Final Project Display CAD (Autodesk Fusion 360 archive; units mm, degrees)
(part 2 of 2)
sketch "Sketch40" plane through (0, 0, 0) normal (0, -1, 0) x axis (1, 0, 0)
  line L1 (-95.12, 65.595) -> (95.12, 65.595)
  line L2 (-95.12, -65.595) -> (-95.12, 65.595)
  line L3 (95.12, -65.595) -> (-95.12, -65.595)
  line L4 (95.12, 65.595) -> (95.12, -65.595)
  circle C1 centre (-90.12, 60.595) radius 2.25
extrude "Extrude52" cut sketch "Sketch40" profile of C1 against normal blind 10
component_from_bodies "Body->Comp4"
offset_faces "OffsetFaces1"
offset_faces "OffsetFaces1"
fillet "Fillet1" radius 0.5
fillet "Fillet1" radius 0.5 0.5
mirror "Mirror8" mirrorStitchTolerance 0.1
copy_paste "CutPaste1"
copy_paste "CutPaste2"
mirror_component "MirrorComponent2"
derived_instance "DerivedInstance3"
derived_instance "DerivedInstance1"
derived_instance "DerivedInstance2"
component_from_bodies "Body->Comp5"
split "Split9" bodies "Suction Cup", "Suction Cup (1)", "Suction Cup (2)", "Suction Cup (3)"
move "Move5"
extrude "Extrude53" cut of existing geometry blind -20
sketch "Sketch41" plane through (0, 6.35, 0) normal (0, 1, 0) x axis (-1, 0, 0)
  line L1 (147.12, -97.595) -> (-147.12, -97.595)
  line L2 (147.12, 137.595) -> (147.12, -97.595)
  line L3 (-147.12, 137.595) -> (147.12, 137.595)
  line L4 (-147.12, -97.595) -> (-147.12, 137.595)
  line L5 (107.12, 53.595) -> (107.12, 67.595)
  line L6 (97.12, 53.595) -> (107.12, 53.595)
  line L7 (97.12, -67.595) -> (97.12, 53.595)
  line L8 (-97.12, -67.595) -> (97.12, -67.595)
  line L9 (-97.12, 53.595) -> (-97.12, -67.595)
  line L10 (-107.12, 53.595) -> (-97.12, 53.595)
  line L11 (-107.12, 67.595) -> (-107.12, 53.595)
  line L12 (107.12, 67.595) -> (-107.12, 67.595)
  circle C1 centre (-135.5, 88.1) radius 2
  circle C2 centre (-126.5, 88.1) radius 2
  circle C3 centre (-135.5, 13.9214) radius 2
  circle C4 centre (-126.5, 13.9214) radius 2
  circle C5 centre (102.62, 71.595) radius 2
  circle C6 centre (-102.62, 71.595) radius 2
  circle C7 centre (-122.2834, -73.1497) radius 14.8661
  circle C8 centre (-122.2834, 113.1497) radius 14.8661
  circle C9 centre (122.2834, 113.1497) radius 14.8661
  circle C10 centre (122.2834, -73.1497) radius 14.8661
  circle C11 centre (-122.2834, 113.1497) radius 2
  circle C12 centre (-122.2834, -73.1497) radius 2
  circle C13 centre (122.2834, -73.1497) radius 2
  circle C14 centre (122.2834, 113.1497) radius 2
  concentric C8 C11
  concentric C7 C12
  concentric C10 C13
  concentric C9 C14
  dimension "d290" diameter C11 = 4
  dimension "d291" diameter C12 = 4
  dimension "d292" diameter C13 = 4
  dimension "d293" diameter C14 = 4
extrude "Extrude54" cut sketch "Sketch41" profile of C11 C12 C13 C14 to an object
component_from_bodies "Body->Comp6"
component_from_bodies "Body->Comp7"
sketch "Laser Cut Frame" plane through (0, 3.175, 0) normal (0, -1, 0) x axis (1, 0, 0)
  line L1 (107.12, 67.595) -> (-107.12, 67.595)
  line L2 (107.12, 53.595) -> (107.12, 67.595)
  line L3 (97.12, 53.595) -> (107.12, 53.595)
  line L4 (97.12, -67.595) -> (97.12, 53.595)
  line L5 (-97.12, -67.595) -> (97.12, -67.595)
  line L6 (-97.12, 53.595) -> (-97.12, -67.595)
  line L7 (-107.12, 53.595) -> (-97.12, 53.595)
  line L8 (-107.12, 67.595) -> (-107.12, 53.595)
  line L9 (147.12, -97.595) -> (-147.12, -97.595)
  line L10 (147.12, 137.595) -> (147.12, -97.595)
  line L11 (-147.12, 137.595) -> (147.12, 137.595)
  line L12 (-147.12, -97.595) -> (-147.12, 137.595)
  circle C1 centre (122.2834, -73.1497) radius 2
  circle C2 centre (-122.2834, -73.1497) radius 2
  circle C3 centre (122.2834, 113.1497) radius 2
  circle C4 centre (-122.2834, 113.1497) radius 2
  circle C5 centre (126.5, 13.9214) radius 2
  circle C6 centre (135.5, 13.9214) radius 2
  circle C7 centre (135.5, 88.1) radius 2
  circle C8 centre (126.5, 88.1) radius 2
  circle C9 centre (-102.62, 71.595) radius 2
  circle C10 centre (102.62, 71.595) radius 2
sketch "Sketch43" plane through (0, 3.175, 0) normal (0, -1, 0) x axis (1, 0, 0)
  line L1 (107.12, 67.595) -> (-107.12, 67.595)
  line L2 (107.12, 53.595) -> (107.12, 67.595)
  line L3 (97.12, 53.595) -> (107.12, 53.595)
  line L4 (97.12, -67.595) -> (97.12, 53.595)
  line L5 (-97.12, -67.595) -> (97.12, -67.595)
  line L6 (-97.12, 53.595) -> (-97.12, -67.595)
  line L7 (-107.12, 53.595) -> (-97.12, 53.595)
  line L8 (-107.12, 67.595) -> (-107.12, 53.595)
  line L9 (147.12, -97.595) -> (-147.12, -97.595)
  line L10 (147.12, 137.595) -> (147.12, -97.595)
  line L11 (-147.12, 137.595) -> (147.12, 137.595)
  line L12 (-147.12, -97.595) -> (-147.12, 137.595)
  line L13 (-75, 127.595) -> (75, 127.595)
  line L14 (-75, 87.595) -> (-75, 127.595)
  line L15 (75, 87.595) -> (-75, 87.595)
  line L16 (75, 127.595) -> (75, 87.595)
  line L17 (-75, 87.595) -> (75, 127.595)
  line L18 (75, 87.595) -> (-75, 127.595)
  line L19 (147.12, 137.595) -> (-147.12, 137.595)
  line L20 (0, 167.595) -> (0, 107.595)
  circle C1 centre (122.2834, -73.1497) radius 2
  circle C2 centre (-122.2834, -73.1497) radius 2
  circle C3 centre (122.2834, 113.1497) radius 2
  circle C4 centre (-122.2834, 113.1497) radius 2
  circle C5 centre (126.5, 13.9214) radius 2
  circle C6 centre (135.5, 13.9214) radius 2
  circle C7 centre (135.5, 88.1) radius 2
  circle C8 centre (126.5, 88.1) radius 2
  circle C9 centre (-102.62, 71.595) radius 2
  circle C10 centre (102.62, 71.595) radius 2
  point P28 (0, 107.595)
  point P31 (0, 107.595)
  point P26 (-75, 87.595)
  point P27 (75, 87.595)
  point P25 (-75, 127.595)
  horizontal L13
  perpendicular L13 L14
  parallel L13 L15
  parallel L14 L16
  coincident L17 P28
  coincident L18 P28
  coincident P28 P31
  perpendicular L19 L20
  midpoint L11 L20
  dimension "d296" distance P26 P27 = 150
  dimension "d297" distance P25 P26 = 40
  dimension "d309" distance L11 L13 = 10
extrude "Extrude1" add sketch "Sketch43" profile of L13 L14 L15 L16 along normal blind 60
split "Split1"
shell "Shell1" innerThickness 2
position "Position4"
sketch "Sketch44" plane through (0, 2.9298, 0) normal (0, -1, 0) x axis (1, 0, 0)
  line L1 (106.5117, 68.1997) -> (-107.7283, 68.1997)
  line L2 (106.5117, 54.1997) -> (106.5117, 68.1997)
  line L3 (96.5117, 54.1997) -> (106.5117, 54.1997)
  line L4 (96.5117, -66.9903) -> (96.5117, 54.1997)
  line L5 (-97.7283, -66.9903) -> (96.5117, -66.9903)
  line L6 (-97.7283, 54.1997) -> (-97.7283, -66.9903)
  line L7 (-107.7283, 54.1997) -> (-97.7283, 54.1997)
  line L8 (-107.7283, 68.1997) -> (-107.7283, 54.1997)
  line L9 (146.5117, -96.9903) -> (-147.7283, -96.9903)
  line L10 (146.5117, 138.1997) -> (146.5117, -96.9903)
  line L11 (-147.7283, 138.1997) -> (146.5117, 138.1997)
  line L12 (-147.7283, -96.9903) -> (-147.7283, 138.1997)
  line L13 (-0.6083, 70.1997) -> (-0.6083, 68.1997)
  line L14 (-3.8631, 70.1997) -> (-0.6083, 70.1997)
  line L15 (11.6417, 71.6997) -> (-12.8583, 71.6997)
  line L16 (-0.6083, 71.6997) -> (-0.6083, 70.1997)
  line L17 (-0.6083, 76.9497) -> (-0.6083, 71.6997)
  line L18 (7, 76.9497) -> (-0.6083, 76.9497)
  circle C1 centre (121.6751, -72.545) radius 2
  circle C2 centre (-122.8918, -72.545) radius 2
  circle C3 centre (121.6751, 113.7544) radius 2
  circle C4 centre (-122.8918, 113.7544) radius 2
  circle C5 centre (125.8917, 14.5261) radius 2
  circle C6 centre (134.8917, 14.5261) radius 2
  circle C7 centre (134.8917, 88.7047) radius 2
  circle C8 centre (125.8917, 88.7047) radius 2
  circle C9 centre (-103.2283, 72.1997) radius 2
  circle C10 centre (102.0117, 72.1997) radius 2
  circle C11 centre (-12.8583, 71.6997) radius 1.5
  circle C12 centre (11.6417, 71.6997) radius 1.5
  circle C13 centre (11.6417, 82.1997) radius 1.5
  circle C14 centre (-12.8583, 82.1997) radius 1.5
  point P24 (-0.6083, 68.1997)
  point P26 (-12.8583, 71.6997)
  point P29 (-12.8583, 71.6997)
  point P27 (11.6417, 71.6997)
  point P30 (11.6417, 71.6997)
  point P31 (-0.6083, 71.6997)
  point P28 (-3.8631, 70.1997)
  point P32 (-3.8631, 70.1997)
  point P33 (-0.6083, 71.6997)
  point P34 (-0.6083, 71.6997)
  point P25 (-0.6083, 70.1997)
  point P35 (-0.6083, 76.9497)
  midpoint L1 P24
  perpendicular L1 L13
  perpendicular L13 L14
  tangent C11 L14
  tangent C12 L14
  coincident P26 P29
  coincident P27 P30
  midpoint L15 P31
  coincident P28 P32
  coincident P31 P33
  vertical L16
  coincident P31 P34
  perpendicular L15 L17
  perpendicular L17 L18
  symmetric C11 L18 C14
  symmetric C12 L18 C13
  dimension "d301" distance P24 P25 = 2
  dimension "d304" distance C11 C12 = 21.5
  dimension "d306" diameter C12 = 3
  dimension "d307" diameter C11 = 3
  dimension "d308" distance P34 P35 = 5.25 (= "( 10.5 / 2 ) * 1 mm")
extrude "Extrude2" cut sketch "Sketch44" profile of C11 C12 C13 C14 against normal blind 10
sketch "Sketch45" plane through (0, 0, 88.1997) normal (0, 0, -1) x axis (1, 0, 0)
  line L1 (74.3917, -2.9298) -> (-75.6083, -2.9298)
  line L2 (74.3917, 57.0702) -> (74.3917, -2.9298)
  line L3 (-75.6083, 57.0702) -> (74.3917, 57.0702)
  line L4 (-75.6083, -2.9298) -> (-75.6083, 57.0702)
  line L5 (-9, 4.0702) -> (9, 4.0702)
  line L6 (-9, 1.0702) -> (-9, 4.0702)
  line L7 (9, 1.0702) -> (-9, 1.0702)
  line L8 (9, 4.0702) -> (9, 1.0702)
  line L9 (-9, 1.0702) -> (9, 4.0702)
  line L10 (9, 1.0702) -> (-9, 4.0702)
  point P10 (0, 2.5702)
  point P8 (-9, 1.0702)
  point P9 (9, 1.0702)
  point P7 (-9, 4.0702)
  horizontal L5
  perpendicular L5 L6
  parallel L5 L7
  parallel L6 L8
  coincident L9 P10
  coincident L10 P10
  dimension "d316" distance P8 P9 = 18
  dimension "d317" distance P7 P8 = 3
  dimension "d318" distance L1 L7 = 4
extrude "Extrude3" cut sketch "Sketch45" profile of L5 L6 L7 L8 to an object
sketch "Sketch46" plane through (0, 0.9298, 0) normal (0, -1, 0) x axis (1, 0, 0)
  line L1 (72.3917, 90.1997) -> (-73.6083, 90.1997)
  line L2 (72.3917, 126.1997) -> (72.3917, 90.1997)
  line L3 (-73.6083, 126.1997) -> (72.3917, 126.1997)
  line L4 (-73.6083, 90.1997) -> (-73.6083, 126.1997)
  line L5 (-68.6083, 126.1997) -> (-73.6083, 126.1997)
  line L6 (-68.6083, 121.1997) -> (-68.6083, 126.1997)
  line L7 (-73.6083, 121.1997) -> (-68.6083, 121.1997)
  line L8 (-73.6083, 126.1997) -> (-73.6083, 121.1997)
  circle C1 centre (-68.6083, 121.1997) radius 1.75
  point P5 (-73.6083, 126.1997)
  point P6 (-73.6083, 126.1997)
  point P8 (-68.6083, 121.1997)
  point P10 (-68.6083, 121.1997)
  point P7 (-68.6083, 126.1997)
  point P9 (-73.6083, 121.1997)
  horizontal L5
  vertical L6
  horizontal L7
  vertical L8
  coincident P5 P6
  coincident P8 P10
  dimension "d319" distance P6 P7 = 5
  dimension "d320" distance P6 P9 = 5
  dimension "d321" diameter C1 = 3.5
extrude "Extrude4" cut sketch "Sketch46" profile of L6 L7 C1 against normal blind 10
work_plane "WorkPlane6"
mirror "Mirror1" mirrorStitchTolerance 0.1
work_plane "WorkPlane7"
mirror "Mirror2" mirrorStitchTolerance 0.1
sketch "Sketch47" plane through (0, 0.9298, 0) normal (0, -1, 0) x axis (1, 0, 0)
  line L1 (72.3917, 90.1997) -> (-73.6083, 90.1997)
  line L2 (72.3917, 126.1997) -> (72.3917, 90.1997)
  line L3 (-73.6083, 126.1997) -> (72.3917, 126.1997)
  line L4 (-73.6083, 90.1997) -> (-73.6083, 126.1997)
  line L5 (-75.6083, 128.1997) -> (74.3917, 128.1997)
  line L6 (74.3917, 128.1997) -> (74.3917, 88.1997)
  line L7 (70.3917, 128.1997) -> (74.3917, 128.1997)
  line L8 (70.3917, 124.1997) -> (70.3917, 128.1997)
  line L9 (74.3917, 124.1997) -> (70.3917, 124.1997)
  line L10 (74.3917, 128.1997) -> (74.3917, 124.1997)
  circle C1 centre (67.3917, 95.1997) radius 1.75
  circle C2 centre (-68.6083, 95.1997) radius 1.75
  circle C3 centre (67.3917, 121.1997) radius 1.75
  circle C4 centre (-68.6083, 121.1997) radius 1.75
  circle C5 centre (72.3917, 126.1997) radius 1.5
  point P8 (72.3917, 126.1997)
  point P10 (72.3917, 126.1997)
  point P11 (74.3917, 128.1997)
  point P14 (74.3917, 128.1997)
  point P15 (70.3917, 128.1997)
  point P17 (74.3917, 124.1997)
  coincident P8 P10
  horizontal L7
  vertical L8
  horizontal L9
  vertical L10
  coincident P11 P14
  dimension "d328" diameter C5 = 3
  dimension "d329" distance P14 P15 = 4
  dimension "d330" distance P14 P17 = 4
extrude "Extrude5" add sketch "Sketch47" profile of L2 L3 L8 L9 along normal blind 58
sketch "Sketch48" plane through (0, -57.0702, 0) normal (0, -1, 0) x axis (1, 0, 0)
  line L1 (-73.6083, 90.1997) -> (72.3917, 90.1997)
  line L2 (-73.6083, 126.1997) -> (-73.6083, 90.1997)
  line L3 (70.3917, 126.1997) -> (-73.6083, 126.1997)
  line L4 (70.3917, 124.1997) -> (70.3917, 126.1997)
  line L5 (72.3917, 124.1997) -> (70.3917, 124.1997)
  line L6 (72.3917, 90.1997) -> (72.3917, 124.1997)
  line L7 (74.3917, 128.1997) -> (74.3917, 88.1997)
  line L8 (-75.6083, 128.1997) -> (74.3917, 128.1997)
  line L9 (-75.6083, 88.1997) -> (-75.6083, 128.1997)
  line L10 (74.3917, 88.1997) -> (-75.6083, 88.1997)
  line L11 (70.3917, 124.1997) -> (74.3917, 128.1997)
  circle C1 centre (72.3917, 126.1997) radius 1.5
  point P9 (74.3917, 128.1997)
  point P12 (74.3917, 128.1997)
  point P6 (70.3917, 124.1997)
  point P13 (70.3917, 124.1997)
  point P14 (72.3917, 126.1997)
  coincident P9 P12
  coincident P6 P13
  midpoint L11 P14
  dimension "d333" diameter C1 = 3
extrude "Extrude6" cut sketch "Sketch48" profile of C1 against normal blind 10
mirror "Mirror3" mirrorStitchTolerance 0.1
mirror "Mirror4" mirrorStitchTolerance 0.1
mirror "Mirror5" mirrorStitchTolerance 0.1
mirror "Mirror6" mirrorStitchTolerance 0.1
mirror "Mirror7" mirrorStitchTolerance 0.1
thread "Thread2"
thread "Thread3"
thread "Thread4"
thread "Thread5"
sketch "Sketch49" plane through (0, -57.0702, 0) normal (0, -1, 0) x axis (1, 0, 0)
  curve K1 (71.4335, 127.0249) -> (71.9931, 124.7091)
  curve K2 (72.7902, 124.7091) -> (73.3498, 127.0249)
  curve K3 (-72.6502, 89.3745) -> (-73.2098, 91.6904)
  curve K4 (-74.0069, 91.6904) -> (-74.5665, 89.3745)
  curve K5 (-72.6502, 125.3745) -> (-73.2098, 127.6904)
  curve K6 (-74.0069, 127.6904) -> (-74.5665, 125.3745)
  line L1 (-71.6083, 90.1997) -> (70.3917, 90.1997)
  line L2 (-71.6083, 92.1997) -> (-71.6083, 90.1997)
  line L3 (-73.6083, 92.1997) -> (-71.6083, 92.1997)
  line L4 (-73.6083, 124.1997) -> (-73.6083, 92.1997)
  line L5 (-71.6083, 124.1997) -> (-73.6083, 124.1997)
  line L6 (-71.6083, 126.1997) -> (-71.6083, 124.1997)
  line L7 (70.3917, 126.1997) -> (-71.6083, 126.1997)
  line L8 (70.3917, 124.1997) -> (70.3917, 126.1997)
  line L9 (72.3917, 124.1997) -> (70.3917, 124.1997)
  line L10 (72.3917, 92.1997) -> (72.3917, 124.1997)
  line L11 (70.3917, 92.1997) -> (72.3917, 92.1997)
  line L12 (70.3917, 90.1997) -> (70.3917, 92.1997)
  line L13 (74.3917, 128.1997) -> (74.3917, 88.1997)
  line L14 (-75.6083, 128.1997) -> (74.3917, 128.1997)
  line L15 (-75.6083, 88.1997) -> (-75.6083, 128.1997)
  line L16 (74.3917, 88.1997) -> (-75.6083, 88.1997)
  line L17 (74.3917, 128.1997) -> (-75.6083, 128.1997)
  line L18 (74.3917, 88.1997) -> (74.3917, 128.1997)
  line L19 (-75.6083, 88.1997) -> (74.3917, 88.1997)
  line L20 (-75.6083, 128.1997) -> (-75.6083, 88.1997)
  arc A1 centre (72.3917, 126.1997) radius 1.2645 clockwise from (71.4335, 127.0249) to (73.3498, 127.0249)
  arc A2 centre (72.3917, 126.1997) radius 1.543 clockwise from (72.7902, 124.7091) to (71.9931, 124.7091)
  arc A3 centre (-73.6083, 90.1997) radius 1.2645 clockwise from (-72.6502, 89.3745) to (-74.5665, 89.3745)
  arc A4 centre (-73.6083, 90.1997) radius 1.543 clockwise from (-74.0069, 91.6904) to (-73.2098, 91.6904)
  arc A5 centre (-73.6083, 126.1997) radius 1.2645 clockwise from (-72.6502, 125.3745) to (-74.5665, 125.3745)
  arc A6 centre (-73.6083, 126.1997) radius 1.543 clockwise from (-74.0069, 127.6904) to (-73.2098, 127.6904)
  circle C1 centre (72.3917, 90.1997) radius 1.2645
  point P30 (74.3917, 88.1997)
  point P36 (74.3917, 88.1997)
  point P32 (-75.6083, 128.1997)
  point P34 (-75.6083, 128.1997)
  horizontal L17
  vertical L18
  horizontal L19
  vertical L20
  coincident P30 P36
  coincident P32 P34
extrude "Extrude7" new body sketch "Sketch49" along normal blind 2 bodies "Lid"
component_from_bodies "Body->Comp1"
position "Position5"
copy_paste "CutPaste1"
copy_paste_bodies "CutPasteBodies"
sketch "Sketch50" plane through (74.3801, 0, 0) normal (1, 0, 0) x axis (0, 1, 0)
  line L1 (3.418, 128.0778) -> (3.418, 88.0778)
  line L2 (-56.582, 128.0778) -> (3.418, 128.0778)
  line L3 (-56.582, 88.0778) -> (-56.582, 128.0778)
  line L4 (3.418, 88.0778) -> (-56.582, 88.0778)
  circle C1 centre (-8, 100) radius 2
  dimension "d348" diameter C1 = 4
extrude "Extrude1" cut sketch "Sketch50" profile of C1 to an object
fillet "Fillet1" radius 10
fillet "Fillet3" radius 10
extrude "Extrude8" cut of existing geometry blind -2
extrude "Extrude1" cut of existing geometry blind -2
fillet "Fillet5" radius 1
fillet "Fillet6" radius 1
fillet "Fillet7" radius 2
sketch "Sketch52" plane through (0, 3.418, 0) normal (0, -1, 0) x axis (1, 0, 0)
  line L1 (96.5001, -67.1122) -> (96.5001, 44.0778)
  line L2 (-97.7399, -67.1122) -> (96.5001, -67.1122)
  line L3 (-97.7399, 44.0778) -> (-97.7399, -67.1122)
  line L4 (-109.7399, 67.0778) -> (-109.7399, 56.0778)
  line L5 (107.5001, 68.0778) -> (-108.7399, 68.0778)
  line L6 (108.5001, 56.0778) -> (108.5001, 67.0778)
  line L7 (146.5001, -97.1122) -> (-147.7399, -97.1122)
  line L8 (146.5001, 138.0778) -> (146.5001, -97.1122)
  line L9 (-147.7399, 138.0778) -> (146.5001, 138.0778)
  line L10 (-147.7399, -97.1122) -> (-147.7399, 138.0778)
  line L11 (98.12, 64.595) -> (86.12, 64.595)
  line L12 (98.12, 76) -> (98.12, 64.595)
  line L13 (100.0001, 72.0778) -> (98.12, 72.0778)
  line L14 (100.0001, 75.5871) -> (100.0001, 72.0778)
  line L15 (85.1799, 77.595) -> (99.0601, 77.595)
  line L16 (85.1799, 77.7532) -> (85.1799, 77.595)
  line L17 (99.0601, 64.595) -> (99.0601, 77.595)
  line L18 (99.0601, 72.0778) -> (99.0601, 68.0778)
  line L19 (85.1799, 68.0778) -> (85.1799, 77.7532)
  line L20 (99.0601, 77.595) -> (99.0601, 72.0778)
  arc A1 centre (106.5001, 44.0778) radius 10 clockwise from (96.5001, 44.0778) to (106.5001, 54.0778)
  arc A2 centre (-107.7399, 44.0778) radius 10 clockwise from (-107.7399, 54.0778) to (-97.7399, 44.0778)
  arc A3 centre (-107.7399, 56.0778) radius 2 clockwise from (-107.7399, 54.0778) to (-109.7399, 56.0778)
  arc A4 centre (-108.7399, 67.0778) radius 1 clockwise from (-109.7399, 67.0778) to (-108.7399, 68.0778)
  arc A5 centre (107.5001, 67.0778) radius 1 clockwise from (107.5001, 68.0778) to (108.5001, 67.0778)
  arc A6 centre (106.5001, 56.0778) radius 2 clockwise from (108.5001, 56.0778) to (106.5001, 54.0778)
  circle C1 centre (67.3801, 95.0778) radius 1.75
  circle C2 centre (-68.6199, 95.0778) radius 1.75
  circle C3 centre (67.3801, 121.0778) radius 1.75
  circle C4 centre (-68.6199, 121.0778) radius 1.75
  circle C5 centre (-12.8699, 82.0778) radius 1.5
  circle C6 centre (-12.8699, 71.5778) radius 1.5
  circle C7 centre (11.6301, 82.0778) radius 1.5
  circle C8 centre (11.6301, 71.5778) radius 1.5
  circle C9 centre (121.6636, -72.667) radius 2
  circle C10 centre (-122.9033, -72.667) radius 2
  circle C11 centre (121.6636, 113.6325) radius 2
  circle C12 centre (-122.9033, 113.6325) radius 2
  circle C13 centre (125.8802, 14.4042) radius 2
  circle C14 centre (134.8802, 14.4042) radius 2
  circle C15 centre (134.8802, 88.5828) radius 2
  circle C16 centre (125.8802, 88.5828) radius 2
  circle C17 centre (-103.2399, 72.0778) radius 2
  circle C18 centre (102.0001, 72.0778) radius 2
  point P43 (98.12, 64.595)
  point P44 (98.12, 64.595)
  point P46 (98.12, 72.0778)
  point P47 (100.0001, 72.0778)
  point P52 (99.0601, 64.595)
  point P53 (99.0601, 68.0778)
  point P54 (99.0601, 72.0778)
  point P55 (85.1799, 68.0778)
  point P49 (99.0601, 77.595)
  point P42 (86.12, 64.595)
  point P51 (85.1799, 77.7532)
  coincident P43 P44
  perpendicular L11 L12
  coincident L12 P46
  coincident C18 P47
  perpendicular L12 L13
  tangent C18 L14
  vertical L14
  perpendicular L15 L16
  perpendicular L15 L17
  coincident L11 P52
  vertical L17
  coincident L17 P53
  coincident L5 P53
  midpoint L13 P54
  coincident L5 P55
  perpendicular L5 L19
  dimension "d371" distance P49 P52 = 13
  dimension "d372" distance P46 P47 = 1.8801
  dimension "d373" distance L12 L17 = 0.9401 (= "d372 / 2")
  dimension "d374" distance P42 P51 = 0.9401 (= "d373")
extrude "Extrude10" cut sketch "Sketch52" profile of L5 L15 L18 L19 L20 against normal blind 10
fillet "Fillet8" radius 20
fillet "Fillet9" radius 2
fillet "Fillet10" radius 2
mirror "Mirror8" mirrorStitchTolerance 0.1
fillet "Fillet11" radius 2 2
sketch "frame-laser" plane through (0, 3.418, 0) normal (0, -1, 0) x axis (1, 0, 0)
  line L1 (-145.7399, 138.0778) -> (144.5001, 138.0778)
  line L2 (-147.7399, -95.1122) -> (-147.7399, 136.0778)
  line L3 (144.5001, -97.1122) -> (-145.7399, -97.1122)
  line L4 (146.5001, 136.0778) -> (146.5001, -95.1122)
  line L5 (-100.2768, 75.595) -> (-100.2768, 70.0778)
  line L6 (-87.4797, 77.595) -> (-98.2768, 77.595)
  line L7 (68.1473, 68.0778) -> (-69.3639, 68.0778)
  line L8 (97.0601, 77.595) -> (86.263, 77.595)
  line L9 (99.0601, 70.0778) -> (99.0601, 75.595)
  line L10 (107.5001, 68.0778) -> (101.0601, 68.0778)
  line L11 (108.5001, 56.0778) -> (108.5001, 67.0778)
  line L12 (96.5001, -67.1122) -> (96.5001, 44.0778)
  line L13 (-97.7399, -67.1122) -> (96.5001, -67.1122)
  line L14 (-97.7399, 44.0778) -> (-97.7399, -67.1122)
  line L15 (-109.7399, 67.0778) -> (-109.7399, 56.0778)
  line L16 (-102.2768, 68.0778) -> (-108.7399, 68.0778)
  arc A1 centre (144.5001, 136.0778) radius 2 clockwise from (144.5001, 138.0778) to (146.5001, 136.0778)
  arc A2 centre (-145.7399, 136.0778) radius 2 clockwise from (-147.7399, 136.0778) to (-145.7399, 138.0778)
  arc A3 centre (-145.7399, -95.1122) radius 2 clockwise from (-145.7399, -97.1122) to (-147.7399, -95.1122)
  arc A4 centre (144.5001, -95.1122) radius 2 clockwise from (146.5001, -95.1122) to (144.5001, -97.1122)
  arc A5 centre (-102.2768, 70.0778) radius 2 clockwise from (-100.2768, 70.0778) to (-102.2768, 68.0778)
  arc A6 centre (-98.2768, 75.595) radius 2 clockwise from (-100.2768, 75.595) to (-98.2768, 77.595)
  arc A7 centre (-87.4797, 75.595) radius 2 clockwise from (-87.4797, 77.595) to (-85.8328, 76.7298)
  arc A8 centre (-69.3639, 88.0778) radius 20 clockwise from (-69.3639, 68.0778) to (-85.8328, 76.7298)
  arc A9 centre (68.1473, 88.0778) radius 20 clockwise from (84.6161, 76.7298) to (68.1473, 68.0778)
  arc A10 centre (86.263, 75.595) radius 2 clockwise from (84.6161, 76.7298) to (86.263, 77.595)
  arc A11 centre (97.0601, 75.595) radius 2 clockwise from (97.0601, 77.595) to (99.0601, 75.595)
  arc A12 centre (101.0601, 70.0778) radius 2 clockwise from (101.0601, 68.0778) to (99.0601, 70.0778)
  arc A13 centre (107.5001, 67.0778) radius 1 clockwise from (107.5001, 68.0778) to (108.5001, 67.0778)
  arc A14 centre (106.5001, 56.0778) radius 2 clockwise from (108.5001, 56.0778) to (106.5001, 54.0778)
  arc A15 centre (106.5001, 44.0778) radius 10 clockwise from (96.5001, 44.0778) to (106.5001, 54.0778)
  arc A16 centre (-107.7399, 44.0778) radius 10 clockwise from (-107.7399, 54.0778) to (-97.7399, 44.0778)
  arc A17 centre (-107.7399, 56.0778) radius 2 clockwise from (-107.7399, 54.0778) to (-109.7399, 56.0778)
  arc A18 centre (-108.7399, 67.0778) radius 1 clockwise from (-109.7399, 67.0778) to (-108.7399, 68.0778)
  circle C1 centre (102.0001, 72.0778) radius 2
  circle C2 centre (-103.2399, 72.0778) radius 2
  circle C3 centre (125.8802, 88.5828) radius 2
  circle C4 centre (134.8802, 88.5828) radius 2
  circle C5 centre (134.8802, 14.4042) radius 2
  circle C6 centre (125.8802, 14.4042) radius 2
  circle C7 centre (-122.9033, 113.6325) radius 2
  circle C8 centre (121.6636, 113.6325) radius 2
  circle C9 centre (-122.9033, -72.667) radius 2
  circle C10 centre (121.6636, -72.667) radius 2
  circle C11 centre (11.6301, 71.5778) radius 1.5
  circle C12 centre (11.6301, 82.0778) radius 1.5
  circle C13 centre (-12.8699, 71.5778) radius 1.5
  circle C14 centre (-12.8699, 82.0778) radius 1.5
  circle C15 centre (-68.6199, 121.0778) radius 1.75
  circle C16 centre (67.3801, 121.0778) radius 1.75
  circle C17 centre (-68.6199, 95.0778) radius 1.75
  circle C18 centre (67.3801, 95.0778) radius 1.75
sketch "Sketch55" plane through (0, -58.582, 0) normal (0, -1, 0) x axis (1, 0, 0)
  curve K1 (-74.0184, 127.5684) -> (-74.578, 125.2525)
  curve K2 (-72.6617, 125.2525) -> (-73.2213, 127.5684)
  curve K3 (-74.0184, 91.5684) -> (-74.578, 89.2525)
  curve K4 (-72.6617, 89.2525) -> (-73.2213, 91.5684)
  curve K5 (72.7787, 124.5871) -> (73.3383, 126.903)
  curve K6 (71.422, 126.903) -> (71.9816, 124.5871)
  line L1 (74.3801, 88.0778) -> (-75.6199, 88.0778)
  line L2 (74.3801, 128.0778) -> (74.3801, 88.0778)
  line L3 (-75.6199, 128.0778) -> (74.3801, 128.0778)
  line L4 (-75.6199, 88.0778) -> (-75.6199, 128.0778)
  line L5 (-75.6199, 90.0778) -> (-73.6199, 90.0778)
  line L6 (-73.6199, 88.0778) -> (-73.6199, 90.0778)
  line L7 (-75.6199, 126.0778) -> (-73.6199, 126.0778)
  line L8 (-73.6199, 128.0778) -> (-73.6199, 126.0778)
  line L9 (74.3801, 126.0778) -> (72.3801, 126.0778)
  line L10 (72.3801, 128.0778) -> (72.3801, 126.0778)
  line L11 (74.3801, 90.0778) -> (72.3801, 90.0778)
  line L12 (72.3801, 88.0778) -> (72.3801, 90.0778)
  arc A1 centre (-73.6199, 126.0778) radius 1.2645 clockwise from (-72.6617, 125.2525) to (-74.578, 125.2525)
  arc A2 centre (-73.6199, 126.0778) radius 1.543 clockwise from (-74.0184, 127.5684) to (-73.2213, 127.5684)
  arc A3 centre (-73.6199, 90.0778) radius 1.2645 clockwise from (-72.6617, 89.2525) to (-74.578, 89.2525)
  arc A4 centre (-73.6199, 90.0778) radius 1.543 clockwise from (-74.0184, 91.5684) to (-73.2213, 91.5684)
  arc A5 centre (72.3801, 126.0778) radius 1.2645 clockwise from (71.422, 126.903) to (73.3383, 126.903)
  arc A6 centre (72.3801, 126.0778) radius 1.543 clockwise from (72.7787, 124.5871) to (71.9816, 124.5871)
  circle C1 centre (72.3801, 90.0778) radius 1.2645
  circle C2 centre (-73.6199, 90.0778) radius 1.75
  circle C3 centre (-73.6199, 126.0778) radius 1.75
  circle C4 centre (72.3801, 126.0778) radius 1.75
  circle C5 centre (72.3801, 90.0778) radius 1.75
  point P9 (-73.6199, 90.0778)
  point P22 (-73.6199, 90.0778)
  point P23 (-75.6199, 90.0778)
  point P24 (-73.6199, 88.0778)
  point P25 (-73.6199, 90.0778)
  point P4 (-73.6199, 126.0778)
  point P26 (-73.6199, 126.0778)
  point P27 (-75.6199, 126.0778)
  point P28 (-73.6199, 128.0778)
  point P29 (-73.6199, 126.0778)
  point P14 (72.3801, 126.0778)
  point P30 (72.3801, 126.0778)
  point P31 (74.3801, 126.0778)
  point P32 (72.3801, 128.0778)
  point P33 (72.3801, 126.0778)
  point P17 (72.3801, 90.0778)
  point P34 (72.3801, 90.0778)
  point P35 (74.3801, 90.0778)
  point P36 (72.3801, 88.0778)
  point P37 (72.3801, 90.0778)
  coincident P9 P22
  coincident L4 P23
  perpendicular L4 L5
  coincident L1 P24
  perpendicular L1 L6
  coincident P22 P25
  coincident P4 P26
  coincident L4 P27
  perpendicular L4 L7
  coincident L3 P28
  perpendicular L3 L8
  coincident P26 P29
  coincident P14 P30
  coincident L2 P31
  perpendicular L2 L9
  coincident L3 P32
  perpendicular L3 L10
  coincident P30 P33
  coincident P17 P34
  coincident L2 P35
  perpendicular L2 L11
  coincident L1 P36
  perpendicular L1 L12
  coincident P34 P37
  dimension "d391" diameter C2 = 3.5
  dimension "d392" diameter C3 = 3.5
  dimension "d393" diameter C4 = 3.5
  dimension "d394" diameter C5 = 3.5
extrude "Extrude2" cut sketch "Sketch55" profile of A1 K1 A2 K2 A3 K3 A4 K4 A5 K5 A6 K6 C1 C2 C3 C4 C5 against normal blind 10
sketch "Sketch56" plane through (0, -58.582, 0) normal (0, -1, 0) x axis (1, 0, 0)
  line L1 (74.3801, 88.0778) -> (-75.6199, 88.0778)
  line L2 (74.3801, 128.0778) -> (74.3801, 88.0778)
  line L3 (-75.6199, 128.0778) -> (74.3801, 128.0778)
  line L4 (-75.6199, 88.0778) -> (-75.6199, 128.0778)
  line L5 (77.3801, 85.0778) -> (-78.6199, 85.0778)
  line L6 (77.3801, 131.0778) -> (77.3801, 85.0778)
  line L7 (-78.6199, 131.0778) -> (77.3801, 131.0778)
  line L8 (-78.6199, 85.0778) -> (-78.6199, 131.0778)
  circle C1 centre (72.3801, 126.0778) radius 1.75
  circle C2 centre (-73.6199, 126.0778) radius 1.75
  circle C3 centre (72.3801, 90.0778) radius 1.75
  circle C4 centre (-73.6199, 90.0778) radius 1.75
  dimension "d397" = 3
extrude "Extrude3" add sketch "Sketch56" profile of L1 L2 L3 L4 L5 L8 L6 L7 to an object
fillet "Fillet1" radius 2
sketch "Sketch57" plane through (0, -58.582, 0) normal (0, -1, 0) x axis (1, 0, 0)
  line L1 (75.3801, 85.0778) -> (-76.6199, 85.0778)
  line L2 (77.3801, 129.0778) -> (77.3801, 87.0778)
  line L3 (-76.6199, 131.0778) -> (75.3801, 131.0778)
  line L4 (-78.6199, 87.0778) -> (-78.6199, 129.0778)
  line L5 (76.7944, 85.6635) -> (-78.0341, 130.492)
  arc A1 centre (-76.6199, 87.0778) radius 2 clockwise from (-76.6199, 85.0778) to (-78.6199, 87.0778)
  arc A2 centre (75.3801, 87.0778) radius 2 clockwise from (77.3801, 87.0778) to (75.3801, 85.0778)
  arc A3 centre (75.3801, 129.0778) radius 2 clockwise from (75.3801, 131.0778) to (77.3801, 129.0778)
  arc A4 centre (-76.6199, 129.0778) radius 2 clockwise from (-78.6199, 129.0778) to (-76.6199, 131.0778)
  circle C1 centre (72.3801, 126.0778) radius 1.75
  circle C2 centre (-73.6199, 126.0778) radius 1.75
  circle C3 centre (72.3801, 90.0778) radius 1.75
  circle C4 centre (-73.6199, 90.0778) radius 1.75
  circle C5 centre (-0.6199, 108.0778) radius 3
  point P18 (-78.0341, 130.492)
  point P19 (76.7944, 85.6635)
  point P20 (-0.6199, 108.0778)
  midpoint A4 P18
  midpoint A2 P19
  midpoint L5 P20
  dimension "d402" diameter C5 = 6
extrude "Extrude4" cut sketch "Sketch57" profile of C5 against normal blind 10
sketch "Sketch59" plane through (-73.6199, 0, 0) normal (1, 0, 0) x axis (0, 1, 0)
  line L1 (-56.582, 124.0778) -> (1.418, 124.0778)
  line L2 (-56.582, 92.0778) -> (-56.582, 124.0778)
  line L3 (1.418, 92.0778) -> (-56.582, 92.0778)
  line L4 (1.418, 124.0778) -> (1.418, 92.0778)
  line L5 (-55.582, 108.0778) -> (-56.582, 108.0778)
  line L6 (-55.582, 101.0778) -> (-55.582, 108.0778)
  line L7 (-55.582, 115.0778) -> (-55.582, 108.0778)
  line L8 (-54.582, 101.0778) -> (-55.582, 101.0778)
  circle C1 centre (-54.582, 101.0778) radius 1
  circle C2 centre (-54.582, 115.0778) radius 1
  circle C3 centre (-54.582, 101.0778) radius 1.25
  circle C4 centre (-54.582, 115.0778) radius 1.25
  point P6 (-56.582, 108.0778)
  point P10 (-54.582, 101.0778)
  point P11 (-54.582, 101.0778)
  point P7 (-55.582, 108.0778)
  point P8 (-55.582, 101.0778)
  point P9 (-55.582, 115.0778)
  midpoint L2 P6
  perpendicular L2 L5
  perpendicular L5 L6
  perpendicular L5 L7
  tangent L6 C1
  coincident P10 P11
  horizontal L8
  symmetric L5 C1 C2
  concentric C1 C3
  concentric C2 C4
  dimension "d405" distance P6 P7 = 1
  dimension "d406" distance P7 P8 = 7
  dimension "d407" distance P7 P9 = 7
  dimension "d408" diameter C1 = 2
  dimension "d409" diameter C3 = 2.5
  dimension "d410" diameter C4 = 2.5
extrude "Extrude5" cut sketch "Sketch59" profile of C3 C4 against normal blind 10
sketch "Sketch60" plane through (0, -58.582, 0) normal (0, -1, 0) x axis (1, 0, 0)
  line L1 (75.3801, 85.0778) -> (-76.6199, 85.0778)
  line L2 (77.3801, 129.0778) -> (77.3801, 87.0778)
  line L3 (-76.6199, 131.0778) -> (75.3801, 131.0778)
  line L4 (-78.6199, 87.0778) -> (-78.6199, 129.0778)
  line L5 (-73.6199, 124.0778) -> (-73.6199, 92.0778)
  line L6 (-72.6199, 108.0778) -> (-73.6199, 108.0778)
  line L7 (-72.6199, 103.5778) -> (-72.6199, 108.0778)
  line L8 (-69.1199, 103.5778) -> (-72.6199, 103.5778)
  line L9 (-69.1199, 103.5778) -> (-72.6199, 103.5778)
  line L10 (-69.1199, 112.5778) -> (-69.1199, 103.5778)
  line L11 (-72.6199, 112.5778) -> (-69.1199, 112.5778)
  line L12 (-72.6199, 103.5778) -> (-72.6199, 112.5778)
  circle C1 centre (-0.6199, 108.0778) radius 3
  arc A1 centre (-76.6199, 87.0778) radius 2 clockwise from (-76.6199, 85.0778) to (-78.6199, 87.0778)
  arc A2 centre (75.3801, 87.0778) radius 2 clockwise from (77.3801, 87.0778) to (75.3801, 85.0778)
  arc A3 centre (75.3801, 129.0778) radius 2 clockwise from (75.3801, 131.0778) to (77.3801, 129.0778)
  arc A4 centre (-76.6199, 129.0778) radius 2 clockwise from (-78.6199, 129.0778) to (-76.6199, 131.0778)
  circle C2 centre (72.3801, 126.0778) radius 1.75
  circle C3 centre (-73.6199, 126.0778) radius 1.75
  circle C4 centre (72.3801, 90.0778) radius 1.75
  circle C5 centre (-73.6199, 90.0778) radius 1.75
  point P21 (-73.6199, 108.0778)
  point P22 (-72.6199, 108.0778)
  point P23 (-72.6199, 103.5778)
  point P24 (-69.1199, 103.5778)
  point P25 (-69.1199, 103.5778)
  point P27 (-72.6199, 112.5778)
  midpoint L5 P21
  perpendicular L5 L6
  perpendicular L6 L7
  perpendicular L7 L8
  horizontal L9
  vertical L10
  horizontal L11
  vertical L12
  dimension "d413" distance P21 P22 = 1
  dimension "d414" distance P22 P23 = 4.5
  dimension "d415" distance P23 P24 = 3.5
  dimension "d416" distance P23 P25 = 3.5
  dimension "d417" distance P23 P27 = 9
extrude "Extrude6" cut sketch "Sketch60" profile of L7 L8 L9 L10 L11 L12 against normal blind 10
fillet "Fillet2" radius 1
position "Position6"
sketch "Sketch61" plane through (0, -56.54, 0) normal (0, -1, 0) x axis (1, 0, 0)
  curve K1 (71.4082, 126.7865) -> (71.9678, 124.4707)
  curve K2 (72.7649, 124.4707) -> (73.3245, 126.7865)
  curve K3 (-72.6755, 89.1361) -> (-73.2351, 91.452)
  curve K4 (-74.0322, 91.452) -> (-74.5918, 89.1361)
  curve K5 (-72.6755, 125.1361) -> (-73.2351, 127.452)
  curve K6 (-74.0322, 127.452) -> (-74.5918, 125.1361)
  line L1 (-71.6336, 89.9613) -> (70.3664, 89.9613)
  line L2 (-71.6336, 91.9613) -> (-71.6336, 89.9613)
  line L3 (-73.6336, 91.9613) -> (-71.6336, 91.9613)
  line L4 (-73.6336, 123.9613) -> (-73.6336, 91.9613)
  line L5 (-71.6336, 123.9613) -> (-73.6336, 123.9613)
  line L6 (-71.6336, 125.9613) -> (-71.6336, 123.9613)
  line L7 (70.3664, 125.9613) -> (-71.6336, 125.9613)
  line L8 (70.3664, 123.9613) -> (70.3664, 125.9613)
  line L9 (72.3664, 123.9613) -> (70.3664, 123.9613)
  line L10 (72.3664, 91.9613) -> (72.3664, 123.9613)
  line L11 (70.3664, 91.9613) -> (72.3664, 91.9613)
  line L12 (70.3664, 89.9613) -> (70.3664, 91.9613)
  line L13 (74.3664, 127.9613) -> (74.3664, 87.9613)
  line L14 (-75.6336, 127.9613) -> (74.3664, 127.9613)
  line L15 (-75.6336, 87.9613) -> (-75.6336, 127.9613)
  line L16 (74.3664, 87.9613) -> (-75.6336, 87.9613)
  line L17 (77.3664, 84.9613) -> (-78.6336, 84.9613)
  line L18 (77.3664, 130.9613) -> (77.3664, 84.9613)
  line L19 (-80, 130.9613) -> (77.3664, 130.9613)
  line L20 (-78.6336, 84.9613) -> (-78.6336, 133)
  line L21 (-70.6336, 122.9613) -> (-73.6336, 122.9613)
  line L22 (-70.6336, 125.9613) -> (-70.6336, 122.9613)
  line L23 (-70.6336, 92.9613) -> (-70.6336, 89.9613)
  line L24 (-73.6336, 92.9613) -> (-70.6336, 92.9613)
  line L25 (69.3664, 92.9613) -> (72.3664, 92.9613)
  line L26 (69.3664, 89.9613) -> (69.3664, 92.9613)
  line L27 (69.3664, 122.9613) -> (69.3664, 125.9613)
  line L28 (72.3664, 122.9613) -> (69.3664, 122.9613)
  arc A1 centre (72.3664, 125.9613) radius 1.2645 clockwise from (71.4082, 126.7865) to (73.3245, 126.7865)
  arc A2 centre (72.3664, 125.9613) radius 1.543 clockwise from (72.7649, 124.4707) to (71.9678, 124.4707)
  arc A3 centre (-73.6336, 89.9613) radius 1.2645 clockwise from (-72.6755, 89.1361) to (-74.5918, 89.1361)
  arc A4 centre (-73.6336, 89.9613) radius 1.543 clockwise from (-74.0322, 91.452) to (-73.2351, 91.452)
  arc A5 centre (-73.6336, 125.9613) radius 1.2645 clockwise from (-72.6755, 125.1361) to (-74.5918, 125.1361)
  arc A6 centre (-73.6336, 125.9613) radius 1.543 clockwise from (-74.0322, 127.452) to (-73.2351, 127.452)
  circle C1 centre (72.3664, 89.9613) radius 1.2645
  dimension "d424" = 1
  dimension "d425" = 1
  dimension "d426" = 1
  dimension "d427" = 1
extrude "Extrude7" add sketch "Sketch61" profile of L1 L2 L3 L4 L5 L6 L7 L8 L9 L10 L11 L12 L13 L14 L15 L16 L19 L17 L20 L18 L21 L22 L23 L24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 to an object
fillet "Fillet3" radius 1 1
fillet "Fillet4" radius 2
extrude "Extrude8" cut of existing geometry blind -10
sketch "laser-lid" plane through (0, -58.54, 0) normal (0, -1, 0) x axis (1, 0, 0)
  line L1 (-71.6336, 103.4613) -> (-70.1336, 103.4613)
  line L2 (-72.6336, 111.4613) -> (-72.6336, 104.4613)
  line L3 (-70.1336, 112.4613) -> (-71.6336, 112.4613)
  line L4 (-69.1336, 104.4613) -> (-69.1336, 111.4613)
  line L5 (75.3664, 84.9613) -> (-76.6336, 84.9613)
  line L6 (77.3664, 128.9613) -> (77.3664, 86.9613)
  line L7 (-76.6336, 130.9613) -> (75.3664, 130.9613)
  line L8 (-78.6336, 86.9613) -> (-78.6336, 128.9613)
  arc A1 centre (-71.6336, 104.4613) radius 1 clockwise from (-71.6336, 103.4613) to (-72.6336, 104.4613)
  arc A2 centre (-71.6336, 111.4613) radius 1 clockwise from (-72.6336, 111.4613) to (-71.6336, 112.4613)
  arc A3 centre (-70.1336, 111.4613) radius 1 clockwise from (-70.1336, 112.4613) to (-69.1336, 111.4613)
  arc A4 centre (-70.1336, 104.4613) radius 1 clockwise from (-69.1336, 104.4613) to (-70.1336, 103.4613)
  circle C1 centre (-0.6336, 107.9613) radius 3
  arc A5 centre (-76.6336, 86.9613) radius 2 clockwise from (-76.6336, 84.9613) to (-78.6336, 86.9613)
  arc A6 centre (75.3664, 86.9613) radius 2 clockwise from (77.3664, 86.9613) to (75.3664, 84.9613)
  arc A7 centre (75.3664, 128.9613) radius 2 clockwise from (75.3664, 130.9613) to (77.3664, 128.9613)
  arc A8 centre (-76.6336, 128.9613) radius 2 clockwise from (-78.6336, 128.9613) to (-76.6336, 130.9613)
  circle C2 centre (72.3664, 125.9613) radius 1.75
  circle C3 centre (-73.6336, 125.9613) radius 1.75
  circle C4 centre (72.3664, 89.9613) radius 1.75
  circle C5 centre (-73.6336, 89.9613) radius 1.75
extrude "Extrude9" cut of existing geometry blind -10
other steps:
derived_base_feature "Derived Base Feature1"
derived_base_feature "Derived Base Feature1" bodies "CaseHinge1"
derived_base_feature "Derived Base Feature1" bodies "FrameHinge1"
base_feature "Base Feature1" bodies "Servo Mount"
base_feature "Base Feature1" bodies "Frame"
base_feature "Base Feature1" bodies "Case"
base_feature "Base Feature1" bodies "FrameHinge1"
base_feature "Base Feature1" bodies "CaseHinge1"
base_feature "Base Feature1" bodies "Frame (1)", "Case"
base_feature "Base Feature2" bodies "Lid"
base_feature "Base Feature1" bodies "Servo Arm Attachment"
base_feature "Base Feature1" bodies "Case Attachment"
extrude "Extrude9" cut of existing geometry blind -2
create_component "CreateComponent1"
remove_body "RemoveBody2"
create_component "CreateComponent2"
remove_body "RemoveBody3"
create_component "CreateComponent3"
remove_body "RemoveBody5"
create_component "CreateComponent4"
remove_body "RemoveBody6"
create_component "CreateComponent8"
remove_instance "RemoveInstance1"
remove_instance "RemoveInstance2"
create_component "CreateComponent9"
create_component "CreateComponent10"
create_component "CreateComponent11"
create_component "CreateComponent12"
remove_body "RemoveBody7"
create_component "CreateComponent13"
remove_body "RemoveBody8"
create_component "CreateComponent14"
remove_body "RemoveBody9"
create_component "CreateComponent1"
remove_body "RemoveBody1"
remove_instance "RemoveInstance1"
remove_body "RemoveBody2"
named bodies: "Case", "Frame", "Servo", "Servo Arm Attachment", "Case Attachment", "Case (2)", "Case (3)", "Case (2) (1)", "Case Attachment (1)", "Frame (1)", "FrameHinge1", "Frame (3)", "Frame (4)", "Servo Mount", "Servo Arm Attachment (1)", "Servo Arm Attachment (2)", "Servo Arm Attachment (3)", "Servo Arm Attachment (4)", "Servo Arm Attachment (5)", "Servo Arm Attachment (6)", "Servo Arm Attachment (7)", "Servo Arm Attachment (8)", "Servo Arm Attachment (9)", "Servo Arm Attachment (10)", "Servo Arm Attachment (11)", "Servo Arm Attachment (12)", "Servo Arm Attachment (13)", "Servo Arm Attachment (14)", "Servo Arm Attachment (15)", "Servo Arm Attachment (16)", "Servo Arm Attachment (17)", "Servo Arm Attachment (18)", "Servo Arm Attachment (19)", "Servo Arm Attachment (20)", "Servo Arm Attachment (21)", "Servo Arm Attachment (22)", "Servo Arm Attachment (23)", "Servo Arm Attachment (24)", "Servo Arm Attachment (25)", "Servo Arm Attachment (26)", "Servo Arm Attachment (27)", "Servo Arm Attachment (28)", "Servo Arm Attachment (29)", "Servo Arm Attachment (30)", "Servo Arm Attachment (31)", "Servo Arm Attachment (32)", "Servo Arm Attachment (33)", "Servo Arm Attachment (34)", "Servo Arm Attachment (35)", "Servo Arm Attachment (36)", "Servo Arm Attachment (37)", "Servo Arm Attachment (38)", "Servo Arm Attachment (39)", "Servo Arm Attachment (40)", "CaseHinge1", "Suction Cup", "Suction Cup (1)", "Suction Cup (2)", "Suction Cup (3)", "Lid"

design "STEP214 DIGITAL SERVO ASSEMBLY"
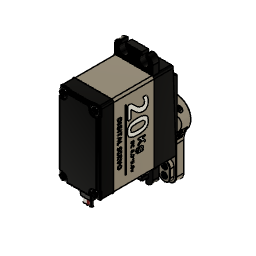
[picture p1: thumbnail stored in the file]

design "M4x2.2mm Hex Nut"
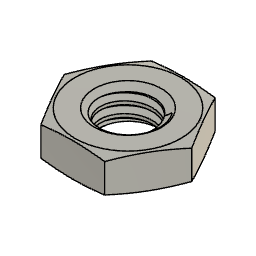
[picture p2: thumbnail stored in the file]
